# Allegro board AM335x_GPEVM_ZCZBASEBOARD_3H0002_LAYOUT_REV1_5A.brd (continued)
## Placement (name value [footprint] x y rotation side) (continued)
R585  10K  [SM-7351-RES-0402]  12.48 75.6 0 bottom
R586  220  [SM-7351-RES-0402]  14.13 86.78 0 top
R587  2.2K  [SM-7351-RES-0402]  11.98 87.92 0 top
R588  10K  [SM-7351-RES-0402]  14.13 87.92 0 top
R589  10K  [SM-7351-RES-0402]  9.05 50.2 180 top
R590  0  [SM-7351-RES-0402]  14.01 81.19 90 bottom
R591  4.7K  [SM-7351-RES-0402]  14.01 83.98 90 bottom
R592  0  [SM-7351-RES-0402]  18.58 68.49 90 top
R593  0  [SM-7351-RES-0402]  16.55 68.49 90 top
R594  100K  [SM-7351-RES-0402]  108.44 57.67 0 top
R595  0  [SM-7351-RES-0402]  104.81 56.55 0 top
R596  10K  [SM-7351-RES-0402]  108.11 52.93 270 bottom
R597  10K  [SM-7351-RES-0402]  110.15 52.93 90 bottom
R598  47  [SM-7351-RES-0402]  93.89 54.01 90 bottom
R599  47  [SM-7351-RES-0402]  90.84 66.71 270 bottom
R600  47  [SM-7351-RES-0402]  96.94 66.71 270 top
R601  47  [SM-7351-RES-0402]  92.87 66.71 270 bottom
R602  47  [SM-7351-RES-0402]  95.92 66.71 270 top
R603  10  [SM-7351-RES-0402]  102.53 51.22 180 bottom
R604  47  [SM-7351-RES-0402]  92.87 66.71 270 top
R605  47  [SM-7351-RES-0402]  86.52 54.01 90 bottom
R606  47  [SM-7351-RES-0402]  90.84 66.71 270 top
R607  47  [SM-7351-RES-0402]  91.86 66.71 270 top
R608  47  [SM-7351-RES-0402]  91.86 54.01 90 bottom
R609  47  [SM-7351-RES-0402]  89.83 66.71 270 top
R610  47  [SM-7351-RES-0402]  90.72 54.01 90 bottom
R611  47  [SM-7351-RES-0402]  89.83 66.71 270 bottom
R612  47  [SM-7351-RES-0402]  89.7 54.01 90 bottom
R613  47  [SM-7351-RES-0402]  88.81 66.71 270 top
R614  47  [SM-7351-RES-0402]  94.91 54.01 90 bottom
R615  47  [SM-7351-RES-0402]  85.51 54.01 90 bottom
R616  47  [SM-7351-RES-0402]  87.67 54.01 90 bottom
R617  47  [SM-7351-RES-0402]  88.81 66.71 270 bottom
R618  47  [SM-7351-RES-0402]  84.49 54.01 90 bottom
R619  47  [SM-7351-RES-0402]  88.68 54.01 90 bottom
R620  47  [SM-7351-RES-0402]  93.89 66.71 270 top
R621  47  [SM-7351-RES-0402]  92.87 54.01 90 bottom
R622  47  [SM-7351-RES-0402]  94.91 66.71 270 top
R623  47  [SM-7351-RES-0402]  91.86 66.71 270 bottom
R624  49.9  [SM-7351-RES-0402]  101 59.09 180 top
R625  49.9  [SM-7351-RES-0402]  101 60.11 180 top
R626  4.7K  [SM-7351-RES-0402]  6.51 50.71 90 top
R627  10K  [SM-7351-RES-0402]  12.86 83.98 270 bottom
R628  10K  [SM-7351-RES-0402]  86.52 27.34 270 bottom
R629  10K  [SM-7351-RES-0402]  13.63 16.17 0 top
R630  10K  [SM-7351-RES-0402]  87.54 62.14 270 bottom
R631  10K  [SM-7351-RES-0402]  78.14 54.27 270 bottom
R632  0  [SM-7351-RES-0402]  71.41 54.14 0 bottom
R634  10K  [SM-7351-RES-0402]  67.86 101.13 90 top
R635  0  [SM-7351-RES-0402]  71.64 57.95 90 top
R636  10K  [SM-7351-RES-0402]  71.41 55.16 0 bottom
SW1  Slide Switch  [TH_SW_T551101]  75.6 10.2 90 top
SW2  B3SL  [SW_B3SL-1022P]  8.8 62.14 270 top
SW3  Switch8pos  [219-8MST]  159.93 60.24 270 top
SW4  Switch8pos  [219-8MST]  159.93 82.84 270 top
SW5  B3SL  [SW_B3SL-1022P]  8.8 44.36 270 top
SW6  B3SL  [SW_B3SL-1022P]  7.4 14.13 0 top
TP23  TP1mm  [TP_SMD1MMCIRCLE]  93.13 98.59 0 top
TP24  TP1mm  [TP_SMD1MMCIRCLE]  69.25 78.02 270 top
TP25  TP  [TH_TP_5002]  88.81 20.36 0 top
TP26  TP  [TH_TP_5002]  100.88 42.07 180 top
TP27  TP  [TH_TP_5002]  4.99 70.4 0 top
TP28  TP  [TH_TP_5002]  167.55 91.35 0 top
TP29  TP  [TH_TP_5002]  91.86 2.7 0 top
TP30  TP  [TH_TP_5002]  85 167.55 0 top
TP31  TP1mm  [TP_SMD1MMCIRCLE]  67.92 95.86 270 top
TP32  TP1mm  [TP_SMD1MMCIRCLE]  63.03 92.87 0 top
TP35  TP1mm  [TP_SMD1MMCIRCLE]  77.38 122.85 180 bottom
TP36  TP1mm  [TP_SMD1MMCIRCLE]  91.35 96.3 0 top
TP38  TP1mm  [TP_SMD1MMCIRCLE]  43.47 61.38 0 top
TP39  TP1mm  [TP_SMD1MMCIRCLE]  43.47 59.98 0 top
TP40  TP1mm  [TP_SMD1MMCIRCLE]  43.47 57.82 0 top
TP41  TP1mm  [TP_SMD1MMCIRCLE]  43.47 56.43 0 top
TP42  TP1mm  [TP_SMD1MMCIRCLE]  14.64 112.94 180 bottom
TP43  TP1mm  [TP_SMD1MMCIRCLE]  13.5 113.58 180 bottom
TP44  TP1mm  [TP_SMD1MMCIRCLE]  14.77 114.21 180 bottom
TP45  TP1mm  [TP_SMD1MMCIRCLE]  3.47 137.45 180 bottom
TP46  TP1mm  [TP_SMD1MMCIRCLE]  31.91 64.43 0 top
TP47  TP1mm  [TP_SMD1MMCIRCLE]  33.18 64.43 0 top
TP48  TP1mm  [TP_SMD1MMCIRCLE]  34.45 64.43 0 top
TP49  TP1mm  [TP_SMD1MMCIRCLE]  35.72 64.43 0 top
TP50  TP1mm  [TP_SMD1MMCIRCLE]  36.36 51.22 180 bottom
TP51  TP1mm  [TP_SMD1MMCIRCLE]  21.12 13.25 0 top
TP52  TP1mm  [TP_SMD1MMCIRCLE]  23.91 75.98 0 top
TP53  TP1mm  [TP_SMD1MMCIRCLE]  85.25 37.5 0 top
TP54  TP  [TH_TP_5002]  139.23 59.85 0 top
U1  SN74AUP1G08  [U_5_DCK]  55.41 102.4 270 top
U2  AM335X_15x15  [AM33XX_15X15]  85 85 90 top
U4  TPS65910A3  [U_48_RSL]  89.45 33.69 90 top
U5  TPS71718  [SMDSC70-5]  84.11 22.52 0 top
U6  SN74AUP2G08  [U_8_DCU]  90.21 23.53 270 top
U7  CAT24C256W  [SOIC_8]  140.31 67.89 0 top
U9  MT29F2G08AB  [SKT-TSOP48SM]  149.01 106.59 90 top
U10  SIL9022A  [QFN_72]  140.88 33.44 180 top
U11  TPD12S016  [PW_24PIN_TSSOP]  140.5 15.02 270 top
U12  TPS71712  [SMDSC70-5]  148.63 18.83 180 top
U13  SN74AVC4T245  [U_16_PW]  23.28 118.4 90 top
U14  SN74AVC4T245  [U_16_PW]  23.28 124.75 90 top
U15  SN74AVC4T245  [U_16_PW]  23.28 137.45 90 top
U16  SN74AVC4T245  [U_16_PW]  23.28 131.1 90 top
U17  TPS79501  [SOT223_6PIN]  8.8 152.69 90 top
U18  MAX3232E  [U_16_D]  109.51 18.58 270 top
U19  TPD6E001  [U_10_RSE]  58.46 144.06 0 top
U20  TPD6E001  [U_10_RSE]  71.92 149.77 90 top
U21  TPD2E001  [U_5_DRL]  64.93 144.56 270 top
U22  TPS2051BD  [U_8_D]  135.42 147.55 0 top
U23  TPD4S012  [U_6_DRY]  132.37 162.32 0 top
U24  TPS63010  [U_20_DSBGA]  155.99 146.85 90 top
U25  AR8031_AL1A  [QFN48]  33.18 55.16 0 top
U26  SN74LVC1G07  [U_5_DCK]  24.17 61.51 90 top
U27  INA226  [SMDMSOP_10]  69.13 47.03 270 bottom
U28  TXS02612  [U_24_RTW]  23.02 108.62 270 top
U29  TPS2051BD  [U_8_D]  143.74 147.23 0 top
U30  TPD4S012  [U_6_DRY]  147.93 161.45 0 top
U32  INA226  [SMDMSOP_10]  64.36 35.15 270 top
U33  MT41J512M8THD  [DDR3_FBGA78PIN]  93.38 60.24 270 top
U34  MT41J512M8THD  [DDR3_FBGA78PIN]  78.78 60.24 270 top
U54  TPS79333  [U_5_DBV]  18.83 95.41 0 top
U55  SN74LVC1G00DCK  [U_5_DCK]  7.4 53.63 180 top
U57  TPD2E001  [U_5_DRL]  8.17 99.86 0 top
U58  FT2232HL  [LQFP64PIN]  15.02 78.27 0 top
U60  SN74LVC2G07  [U_6_DCK]  10.45 53.63 0 top
U61  93LC56B  [SOIC8]  11.85 92.62 90 top
U62  TPS51200  [DRCPSO_10PIN]  104.66 54.95 180 bottom
U63  TPS3808G01  [SOT23-6]  65.06 101 90 top
U64  SN74AVC1T45  [SMDSC70-6]  74.21 53.5 90 bottom
Y1  32.768KHz MC-306  [MC-306]  63.03 76.36 270 top
Y2  24MHz  [SM_CRY_SCC18]  105.7 81.83 0 top
Y3  25MHz  [SM_OSC_ABM3]  24.68 56.17 270 top
Y4  12MHz  [SM_OSC_ABM3]  4.99 85.64 270 top

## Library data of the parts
BT1 = Battery_coin3V
C1 C16 C17 C19 C23-C25 C29-C32 C35 C36 C43 C45-C48 C50 C52 C53 C61 C62 = 0.01uFCapacitor16V10%0402
C2 C3 = 25pFCapacitor100V5%0603
C4 C5 = 18pFCapacitor16V10%0402
C6-C8 C15 C18 C20 C27 C28 C34 C41 C42 C56 C63 C64 C66-C70 C73 C74 C76-C80 C82 C83 C87 C89 C90 C92-C94 C96 C98 C111 C114-C116 C125 C126 C128-C130 C136-C140 C149 C155-C158 C161-C170 C174 C175 C181 C183 C186 C188 C189 C195 C202 C203 C208 C213-C227 C313-C319 C321-C325 C327-C329 C331 = 0.01uFCapacitor16V10%0402: Tolerance: TOLERANCE; User Part Number: USERPART#
C9 = 0.1uFCapacitor16V10%0402
C10 C12 = 0.001uFCapacitor50V5%0402
C11 C13 C85 C86 C127 C131-C135 C141-C148 C150-C154 C176-C180 C187 C190 C193 C194 C196-C201 C209 C260 C264 C303-C309 C334-C336 C338 C339 C352-C357 C360-C379 = 0.1uFCapacitor16V10%0402: Tolerance: TOLERANCE; User Part Number: USERPART#
C14 C340 C341 = 0.001uFCapacitor50V5%0402: Tolerance: TOLERANCE; User Part Number: USERPART#
C60 = 1uFCapacitor10V10%0402
C65 C71 C72 C88 C112 C113 C117 C118 C159 C160 C173 C191 C192 = 1uFCapacitor10V10%0402: Tolerance: TOLERANCE; User Part Number: USERPART#
C84 = 100uFCapacitor16V20%ElectroPoly
C91 C97 C101-C104 C107-C110 C184 = 2.2uFCapacitor6.3V20%smdX5R0402: Tolerance: TOLERANCE; User Part Number: USERPART#
C171 = 15pFCapacitor50V10%smd0402: Tolerance: TOLERANCE; User Part Number: USERPART#
C172 C311 = 2.2uF16V10%SMD0805
C182 C185 = 150uFCapacitor10V10%2917
C204 C212 = 22pFCapacitor50V10%SMD0402: Tolerance: TOLERANCE; User Part Number: USERPART#
C205-C207 = 470pFCapacitor25V10%0402: Tolerance: TOLERANCE; User Part Number: USERPART#
C232-C249 C256-C259 C261 C266 C273-C279 C312 = 10uFCapacitor16V10%0805
C250-C255 = 4.7uFCapacitor6.3V20%smdX5R0603
C262 C263 C265 C320 C326 C330 C358 C359 = 4.7uFCapacitor16V10%0603
C267-C270 C280 = 22uFCapacitor16V10%0805
C271 C272 = 0.1uFCapacitor50V10%0402: Tolerance: TOLERANCE; User Part Number: USERPART#
C332 C333 = 18pFCapacitor16V10%0402: Tolerance: TOLERANCE; User Part Number: USERPART#
C337 = 10pFCapacitor50V1%smd0402: Tolerance: TOLERANCE; User Part Number: USERPART#
D1 = Diode_5ARect
D2 = Diode_SMCJ15CA
D3-D7 D11 = LED_Green
D8 = Diode200mA250V
D9 D10 = Diode_Zener_5.1V_100mW
F1 = Fuse_4A
FB1-FB14 FB19-FB21 FB25 = FerBead_180ohm200mA
FB15 FB16 = FerriteBead_600mA10ohm
FB22-FB24 = FerriteBead_220ohm2A
J1 = Conn_PwrJack_RAPC712
J2 = Header10x2_CJTAG
J3 J4 J6 J16 = Header_28pin_0.1in
J5 = Header_40pin_0.1in
J7-J9 = Header10x2_0.5inpitch_female
J10 = Conn_HDMI_TypeA
J11 = Conn_SamtecMEC6_150
J12 = Conn_DSUB9M_TH
J13 = Conn_SDCard_MHC-W21-601
J14 J40 = Conn_MicroUSBAB
J15 = ConnectorRJ45_Gigabit
J17 = Header_5x1
J18 = Connector_USB_A
J19 = Header20x1_wkey
J20-J39 J41 = Header_2x1
L2-L4 = 2.2uHInductor10%2.6Asmd
L5 L6 = ACM2012
L7 L8 = 4.7uH30%0.9Asmd
L9 = 4.7uHInductor30%3.1Asmd
Q1-Q4 = MOSFET_NChan_BSS138
Q5 = MOSFET_PChan_BSS84
R2 R3 R5 R8-R10 R30 R45 R51 R53 R55-R68 R73-R78 R84 R85 R87-R92 R113 R133-R157 R159 R161 R163 R165 R167 R169 R171 R173 R175-R184 R186 R187 R189 R191 R193 R194 R196-R230 R232-R234 R236 R240-R273 R278-R291 R293-R303 R305 R307 R308 R311-R325 R327 R328 R335-R358 R361-R364 R379 R380 R384 R385 R388 R389 R396-R402 R404 R405 R410 R423-R425 R427 R428 R430 R436-R452 R456-R460 R478 R479 R485-R492 R509-R512 R516 R550 R551 R556 R559-R562 R566 R571 R575-R583 R590 R592 R593 R595 R632 R635 = ZeroOhmResistor1/16W0402
R4 R86 R93-R111 R386 R391 R594 = 100KOhmResistor1/16W0402
R6 R48 R54 R72 R114-R132 R239 R274 R304 R306 R329-R334 R365-R373 R382 R383 R387 R393 R407 R409 R411-R414 R419 R422 R426 R431 R435 R455 R515 R518 R519 R544 R565 R569 R570 R585 R588 R589 R596 R597 R627-R631 R634 R636 = 10KOhmResistor1/16W0402
R7 = 1MOhmResistor1/16W0402
R22 R624 R625 = 49.9OhmResistor1/16W0402
R23 = 124Kohm1/16W1%SMD0402
R32 R46 = 0.05ohm0.5W1%Sense1206
R50 R80-R83 = 150ohm1/16W1%SMD0402
R69 R112 = 1KOhmResistor1/16W0402
R70 R71 R79 R275 R276 R326 R394 R453 R454 R547 R548 R552-R555 R591 R626 = 4.7KOhmResistor1/16W0402
R188 R231 R235 R237 R395 R415-R418 R420 R421 R432-R434 = 22OhmResistor1/16W1%0402
R277 = 51Kohm1/16W1%smd0402
R292 = 4.3KOhmResistor1/16W0402
R359 = 57.6Kohm1/10W1%smd0402
R360 = 30.1Kohm1/16W1%smd0402
R378 = 470Kohm1/16W1%SMD0402
R381 = 120Kohm1/16W1%SMD0402
R390 R392 R586 = 220ohm1/10W1%smd0402
R406 = 2.37KOhmResistor1/16W1%0402
R408 = 1.5KohmResistor1/16W5%smd0402
R461 R462 R517 = 100ohm1/16W1%SMD0402
R463-R477 R557 R558 = ZeroOhmResistor1/16W0603
R493-R496 R498 R508 R513 R545 R546 = 0.24ohm0.25W1%Sense0805
R497 R499 R500 R503-R507 = 2ohm0.25W1%Sense0805
R501 R502 = 1ohm0.25W1%Sense0805
R520 = 1.62MOhmResistor1/16W0402
R521 = 180KOhmResistor1/16W0402
R541 R542 R567 R568 R587 = 2.2KOhmResistor1/16W0402
R563 R564 = 1.2KohmResistor1/4W5%0805
R572 R573 = 240OhmResistor1/16W0402
R584 = 12Kohm1/16W1%SMD0402
R598-R602 R604-R623 = 47ohm1/16W1%smd0402
R603 = 10ohm1/16W5%smd0402
SW1 = Switch_SlideRA_SPDT
SW2 SW5 SW6 = Switch_Pushbuttonsmd
SW3 SW4 = SwitchDIP8pos_smd
TP23 TP24 TP31 TP32 TP35 TP36 TP38-TP53 = Testpoint_SMD1mmCircle
TP25-TP30 TP54 = TestPointThroughHole
U1 = SN74AUP1G08
U2 = AM335X_15mmx15mm
U4 = TPS65910A3
U5 = TPS71718
U6 = SN74AUP2G08
U7 = CAT24C256W
U9 = MT29F2G08ABBE
U10 = SIL9022A
U11 = TPD12S016
U12 = TPS71712
U13-U16 = SN74AVC4T245
U17 = TPS79501
U18 = MAX3232E
U19 U20 = TPD6E001RSE
U21 U57 = TPD2E001DRL
U22 U29 = TPS2051BD
U23 U30 = TPD4S012
U24 = TPS63010YFF
U25 = AR8031-AL1A_QFN48
U26 = SN74LVC1G07
U27 U32 = INA226
U28 = TXS02612
U33 U34 = MT41J512M8THD
U54 = TPS79333
U55 = SN74LVC1G00DCK
U58 = FT2232_2
U60 = SN74LVC2G07
U61 = 93C56EEPROM2Kbit: Tolerance: ***; User Part Number: ***
U62 = TPS51200
U63 = TPS3808G01
U64 = SN74AVC1T45
Y1 = Crystal_SMD32_768kHz
Y2 = Crystal24MHzSCC
Y3 = Crystal25MHzABM3
Y4 = Crystal12MHzABM3

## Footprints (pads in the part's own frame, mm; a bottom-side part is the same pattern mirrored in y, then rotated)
219-8MST
  rect 1.118x2.438 smd: 1(-8.89,-4.318) 2(-6.35,-4.318) 3(-3.81,-4.318) 4(-1.27,-4.318) 5(1.27,-4.318) 6(3.81,-4.318) 7(6.35,-4.318) 8(8.89,-4.318) 9(8.89,4.318) 10(6.35,4.318) 11(3.81,4.318) 12(1.27,4.318) 13(-1.27,4.318) 14(-3.81,4.318) 15(-6.35,4.318) 16(-8.89,4.318)
6605814-6
  round 1.422 hole 0.889: 1(0,0) 2(1.27,-2.54) 3(2.54,0) 4(3.81,-2.54) 5(5.08,0) 6(6.35,-2.54) 7(7.62,0) 8(8.89,-2.54) 9(10.16,0) 10(11.43,-2.54)
  round 1.397 hole 1.016: D1(-1.067,-11.43) D2(-1.067,-13.462) D3(12.497,-11.43) D4(12.497,-13.462)
  round 3.81 hole 3.175: M1(0,-8.89) M2(11.43,-8.89)
  round 2.159 hole 1.575: SHLD1(-2.032,-5.842) SHLD2(13.462,-5.842)
ACM2012H
  rect 0.75x0.35 smd: 1(-0.975,0.425) 2(-0.975,-0.425) 3(0.975,-0.425) 4(0.975,0.425)
AM33XX_15X15
  round 1.27 hole 1.778 unplated: (-9.238,8.863) (-9.238,-8.862) (8.487,8.863) (8.487,-8.862)
  round 1.397 hole 0.838 unplated: (-9.238,-3.782) (8.487,6.323)
  round 0.356 smd: A1(-6.8,6.8) A2(-6,6.8) A3(-5.2,6.8) A4(-4.4,6.8) A5(-3.6,6.8) A6(-2.8,6.8) A7(-2,6.8) A8(-1.2,6.8) A9(-0.4,6.8) A10(0.4,6.8) A11(1.2,6.8) A12(2,6.8) A13(2.8,6.8) A14(3.6,6.8) A15(4.4,6.8) A16(5.2,6.8) A17(6,6.8) A18(6.8,6.8) B1(-6.8,6) B2(-6,6) B3(-5.2,6) B4(-4.4,6) B5(-3.6,6) B6(-2.8,6) B7(-2,6) B8(-1.2,6) B9(-0.4,6) B10(0.4,6) B11(1.2,6) B12(2,6) B13(2.8,6) B14(3.6,6) B15(4.4,6) B16(5.2,6) B17(6,6) B18(6.8,6) C1(-6.8,5.2) C2(-6,5.2) C3(-5.2,5.2) C4(-4.4,5.2) C5(-3.6,5.2) C6(-2.8,5.2) C7(-2,5.2) C8(-1.2,5.2) C9(-0.4,5.2) C10(0.4,5.2) C11(1.2,5.2) C12(2,5.2) C13(2.8,5.2) C14(3.6,5.2) C15(4.4,5.2) C16(5.2,5.2) C17(6,5.2) C18(6.8,5.2) D1(-6.8,4.4) D2(-6,4.4) D3(-5.2,4.4) D4(-4.4,4.4) D5(-3.6,4.4) D6(-2.8,4.4) D7(-2,4.4) D8(-1.2,4.4) D9(-0.4,4.4) D10(0.4,4.4) D11(1.2,4.4) D12(2,4.4) D13(2.8,4.4) D14(3.6,4.4) D15(4.4,4.4) D16(5.2,4.4) D17(6,4.4) D18(6.8,4.4) E1(-6.8,3.6) E2(-6,3.6) E3(-5.2,3.6) E4(-4.4,3.6) E5(-3.6,3.6) E6(-2.8,3.6) E7(-2,3.6) E8(-1.2,3.6) E9(-0.4,3.6) E10(0.4,3.6) E11(1.2,3.6) E12(2,3.6) E13(2.8,3.6) E14(3.6,3.6) E15(4.4,3.6) E16(5.2,3.6) E17(6,3.6) E18(6.8,3.6) F1(-6.8,2.8) F2(-6,2.8) F3(-5.2,2.8) F4(-4.4,2.8) F5(-3.6,2.8) F6(-2.8,2.8) F7(-2,2.8) F8(-1.2,2.8) F9(-0.4,2.8) F10(0.4,2.8) F11(1.2,2.8) F12(2,2.8) F13(2.8,2.8) F14(3.6,2.8) F15(4.4,2.8) F16(5.2,2.8) F17(6,2.8) F18(6.8,2.8) G1(-6.8,2) G2(-6,2) G3(-5.2,2) G4(-4.4,2) G5(-3.6,2) G6(-2.8,2) G7(-2,2) G8(-1.2,2) G9(-0.4,2) G10(0.4,2) G11(1.2,2) G12(2,2) G13(2.8,2) G14(3.6,2) G15(4.4,2) G16(5.2,2) G17(6,2) G18(6.8,2) H1(-6.8,1.2) H2(-6,1.2) H3(-5.2,1.2) H4(-4.4,1.2) H5(-3.6,1.2) H6(-2.8,1.2) H7(-2,1.2) H8(-1.2,1.2) H9(-0.4,1.2) H10(0.4,1.2) H11(1.2,1.2) H12(2,1.2) H13(2.8,1.2) H14(3.6,1.2) H15(4.4,1.2) H16(5.2,1.2) H17(6,1.2) H18(6.8,1.2) J1(-6.8,0.4) J2(-6,0.4) J3(-5.2,0.4) J4(-4.4,0.4) J5(-3.6,0.4) J6(-2.8,0.4) J7(-2,0.4) J8(-1.2,0.4) J9(-0.4,0.4) J10(0.4,0.4) J11(1.2,0.4) J12(2,0.4) J13(2.8,0.4) J14(3.6,0.4) J15(4.4,0.4) J16(5.2,0.4) J17(6,0.4) J18(6.8,0.4) K1(-6.8,-0.4) K2(-6,-0.4) K3(-5.2,-0.4) K4(-4.4,-0.4) K5(-3.6,-0.4) K6(-2.8,-0.4) K7(-2,-0.4) K8(-1.2,-0.4) K9(-0.4,-0.4) K10(0.4,-0.4) K11(1.2,-0.4) K12(2,-0.4) K13(2.8,-0.4) K14(3.6,-0.4) K15(4.4,-0.4) K16(5.2,-0.4) K17(6,-0.4) K18(6.8,-0.4) L1(-6.8,-1.2) L2(-6,-1.2) L3(-5.2,-1.2) L4(-4.4,-1.2) L5(-3.6,-1.2) L6(-2.8,-1.2) L7(-2,-1.2) L8(-1.2,-1.2) L9(-0.4,-1.2) L10(0.4,-1.2) L11(1.2,-1.2) L12(2,-1.2) L13(2.8,-1.2) L14(3.6,-1.2) L15(4.4,-1.2) L16(5.2,-1.2) L17(6,-1.2) L18(6.8,-1.2) M1(-6.8,-2) M2(-6,-2) M3(-5.2,-2) M4(-4.4,-2) M5(-3.6,-2) M6(-2.8,-2) M7(-2,-2) M8(-1.2,-2) M9(-0.4,-2) M10(0.4,-2) M11(1.2,-2) M12(2,-2) M13(2.8,-2) M14(3.6,-2) M15(4.4,-2) M16(5.2,-2) M17(6,-2) M18(6.8,-2) N1(-6.8,-2.8) N2(-6,-2.8) N3(-5.2,-2.8) N4(-4.4,-2.8) N5(-3.6,-2.8) N6(-2.8,-2.8) N7(-2,-2.8) N8(-1.2,-2.8) N9(-0.4,-2.8) N10(0.4,-2.8) N11(1.2,-2.8) N12(2,-2.8) N13(2.8,-2.8) N14(3.6,-2.8) N15(4.4,-2.8) N16(5.2,-2.8) N17(6,-2.8) N18(6.8,-2.8) P1(-6.8,-3.6) P2(-6,-3.6) P3(-5.2,-3.6) P4(-4.4,-3.6) P5(-3.6,-3.6) P6(-2.8,-3.6) P7(-2,-3.6) P8(-1.2,-3.6) P9(-0.4,-3.6) P10(0.4,-3.6) P11(1.2,-3.6) P12(2,-3.6) P13(2.8,-3.6) P14(3.6,-3.6) P15(4.4,-3.6) P16(5.2,-3.6) P17(6,-3.6) P18(6.8,-3.6) R1(-6.8,-4.4) R2(-6,-4.4) R3(-5.2,-4.4) R4(-4.4,-4.4) R5(-3.6,-4.4) R6(-2.8,-4.4) R7(-2,-4.4) R8(-1.2,-4.4) R9(-0.4,-4.4) R10(0.4,-4.4) R11(1.2,-4.4) R12(2,-4.4) R13(2.8,-4.4) R14(3.6,-4.4) R15(4.4,-4.4) R16(5.2,-4.4) R17(6,-4.4) R18(6.8,-4.4) T1(-6.8,-5.2) T2(-6,-5.2) T3(-5.2,-5.2) T4(-4.4,-5.2) T5(-3.6,-5.2) T6(-2.8,-5.2) T7(-2,-5.2) T8(-1.2,-5.2) T9(-0.4,-5.2) T10(0.4,-5.2) T11(1.2,-5.2) T12(2,-5.2) T13(2.8,-5.2) T14(3.6,-5.2) T15(4.4,-5.2) T16(5.2,-5.2) T17(6,-5.2) T18(6.8,-5.2) U1(-6.8,-6) U2(-6,-6) U3(-5.2,-6) U4(-4.4,-6) U5(-3.6,-6) U6(-2.8,-6) U7(-2,-6) U8(-1.2,-6) U9(-0.4,-6) U10(0.4,-6) U11(1.2,-6) U12(2,-6) U13(2.8,-6) U14(3.6,-6) U15(4.4,-6) U16(5.2,-6) U17(6,-6) U18(6.8,-6) V1(-6.8,-6.8) V2(-6,-6.8) V3(-5.2,-6.8) V4(-4.4,-6.8) V5(-3.6,-6.8) V6(-2.8,-6.8) V7(-2,-6.8) V8(-1.2,-6.8) V9(-0.4,-6.8) V10(0.4,-6.8) V11(1.2,-6.8) V12(2,-6.8) V13(2.8,-6.8) V14(3.6,-6.8) V15(4.4,-6.8) V16(5.2,-6.8) V17(6,-6.8) V18(6.8,-6.8)
B520C-13-F
  rect 2.5x3.3 smd: 1(-3.4,0) 2(3.4,0)
CHKFOOTPRINT
  rect 0.8x1.8 smd: 1(-0.8,0) 2(0.8,0)
DDR3_FBGA78PIN
  round 0.33 smd: A1(-3.2,4.8) A2(-2.4,4.8) A3(-1.6,4.8) A7(1.6,4.8) A8(2.4,4.8) A9(3.2,4.8) B1(-3.2,4) B2(-2.4,4) B3(-1.6,4) B7(1.6,4) B8(2.4,4) B9(3.2,4) C1(-3.2,3.2) C2(-2.4,3.2) C3(-1.6,3.2) C7(1.6,3.2) C8(2.4,3.2) C9(3.2,3.2) D1(-3.2,2.4) D2(-2.4,2.4) D3(-1.6,2.4) D7(1.6,2.4) D8(2.4,2.4) D9(3.2,2.4) E1(-3.2,1.6) E2(-2.4,1.6) E3(-1.6,1.6) E7(1.6,1.6) E8(2.4,1.6) E9(3.2,1.6) F1(-3.2,0.8) F2(-2.4,0.8) F3(-1.6,0.8) F7(1.6,0.8) F8(2.4,0.8) F9(3.2,0.8) G1(-3.2,0) G2(-2.4,0) G3(-1.6,0) G7(1.6,0) G8(2.4,0) G9(3.2,0) H1(-3.2,-0.8) H2(-2.4,-0.8) H3(-1.6,-0.8) H7(1.6,-0.8) H8(2.4,-0.8) H9(3.2,-0.8) J1(-3.2,-1.6) J2(-2.4,-1.6) J3(-1.6,-1.6) J7(1.6,-1.6) J8(2.4,-1.6) J9(3.2,-1.6) K1(-3.2,-2.4) K2(-2.4,-2.4) K3(-1.6,-2.4) K7(1.6,-2.4) K8(2.4,-2.4) K9(3.2,-2.4) L1(-3.2,-3.2) L2(-2.4,-3.2) L3(-1.6,-3.2) L7(1.6,-3.2) L8(2.4,-3.2) L9(3.2,-3.2) M1(-3.2,-4) M2(-2.4,-4) M3(-1.6,-4) M7(1.6,-4) M8(2.4,-4) M9(3.2,-4) N1(-3.2,-4.8) N2(-2.4,-4.8) N3(-1.6,-4.8) N7(1.6,-4.8) N8(2.4,-4.8) N9(3.2,-4.8)
DRCPSO_10PIN
  rect 0.305x1.092 smd: 1(-1,-1.625) 2(-0.5,-1.625) 3(0,-1.625) 4(0.5,-1.625) 5(1,-1.625) 6(1,1.625) 7(0.5,1.625) 8(0,1.625) 9(-0.5,1.625) 10(-1,1.625)
  custom 0.412x0.412 smd: 11(0,0)
GMD2_2PIN
  rect 0.31x0.23 smd: 1(0,-0.19) 2(0,0.19)
HEADER10X2
  rect 0.711x2.87 smd: 1(-5.715,-2.705) 2(-5.715,2.705) 3(-4.445,-2.705) 4(-4.445,2.705) 5(-3.175,-2.705) 6(-3.175,2.705) 7(-1.905,-2.705) 8(-1.905,2.705) 9(-0.635,-2.705) 10(-0.635,2.705) 11(0.635,-2.705) 12(0.635,2.705) 13(1.905,-2.705) 14(1.905,2.705) 15(3.175,-2.705) 16(3.175,2.705) 17(4.445,-2.705) 18(4.445,2.705) 19(5.715,-2.705) 20(5.715,2.705)
HEADER20X1_0_100IN
  rect 1.524x1.524 hole 1.016: 1(0,0)
  round 1.524 hole 1.016: 2(2.54,0) 3(5.08,0) 5(10.16,0) 6(12.7,0) 7(15.24,0) 8(17.78,0) 9(20.32,0) 10(22.86,0) 11(25.4,0) 12(27.94,0) 13(30.48,0) 14(33.02,0) 15(35.56,0) 16(38.1,0) 17(40.64,0) 18(43.18,0) 19(45.72,0) 20(48.26,0)
HEADER_2X1
  rect 1.778x1.778 hole 1.016: 1(0,0)
  round 1.778 hole 1.016: 2(0,2.54)
HEADER_5X1
  rect 1.778x1.778 hole 1.016: 1(0,0)
  round 1.778 hole 1.016: 2(2.54,0) 3(5.08,0) 4(7.62,0) 5(10.16,0)
HEADER_10X2_TH
  oval 0.914x1.168 hole 0.66: 1(0,0) 2(0,1.27) 3(1.27,0) 4(1.27,1.27) 5(2.54,0) 6(2.54,1.27) 7(3.81,0) 8(3.81,1.27) 9(5.08,0) 10(5.08,1.27) 11(6.35,0) 12(6.35,1.27) 13(7.62,0) 14(7.62,1.27) 15(8.89,0) 16(8.89,1.27) 17(10.16,0) 18(10.16,1.27) 19(11.43,0) 20(11.43,1.27)
HF70ACB201209
  rect 1x1 smd: 1(-1,0) 2(1,0)
JUMP2X14-6040-1
  round 1.397 hole 1.016: 1(0,0) 2(0,2.54) 3(-2.54,0) 4(-2.54,2.54) 5(-5.08,0) 6(-5.08,2.54) 7(-7.62,0) 8(-7.62,2.54) 9(-10.16,0) 10(-10.16,2.54) 11(-12.7,0) 12(-12.7,2.54) 13(-15.24,0) 14(-15.24,2.54) 15(-17.78,0) 16(-17.78,2.54) 17(-20.32,0) 18(-20.32,2.54) 19(-22.86,0) 20(-22.86,2.54) 21(-25.4,0) 22(-25.4,2.54) 23(-27.94,0) 24(-27.94,2.54) 25(-30.48,0) 26(-30.48,2.54) 27(-33.02,0) 28(-33.02,2.54)
JUMP2X20-6040-1
  round 1.524 hole 1.016: 1(0,0) 2(0,2.54) 3(-2.54,0) 4(-2.54,2.54) 5(-5.08,0) 6(-5.08,2.54) 7(-7.62,0) 8(-7.62,2.54) 9(-10.16,0) 10(-10.16,2.54) 11(-12.7,0) 12(-12.7,2.54) 13(-15.24,0) 14(-15.24,2.54) 15(-17.78,0) 16(-17.78,2.54) 17(-20.32,0) 18(-20.32,2.54) 19(-22.86,0) 20(-22.86,2.54) 21(-25.4,0) 22(-25.4,2.54) 23(-27.94,0) 24(-27.94,2.54) 25(-30.48,0) 26(-30.48,2.54) 27(-33.02,0) 28(-33.02,2.54) 29(-35.56,0) 30(-35.56,2.54) 31(-38.1,0) 32(-38.1,2.54) 33(-40.64,0) 34(-40.64,2.54) 35(-43.18,0) 36(-43.18,2.54) 37(-45.72,0) 38(-45.72,2.54) 39(-48.26,0) 40(-48.26,2.54)
LQFP64PIN
  rect 1.5x0.3 smd: 1(-5.7,3.75) 2(-5.7,3.25) 3(-5.7,2.75) 4(-5.7,2.25) 5(-5.7,1.75) 6(-5.7,1.25) 7(-5.7,0.75) 8(-5.7,0.25) 9(-5.7,-0.25) 10(-5.7,-0.75) 11(-5.7,-1.25) 12(-5.7,-1.75) 13(-5.7,-2.25) 14(-5.7,-2.75) 15(-5.7,-3.25) 16(-5.7,-3.75) 33(5.7,-3.75) 34(5.7,-3.25) 35(5.7,-2.75) 36(5.7,-2.25) 37(5.7,-1.75) 38(5.7,-1.25) 39(5.7,-0.75) 40(5.7,-0.25) 41(5.7,0.25) 42(5.7,0.75) 43(5.7,1.25) 44(5.7,1.75) 45(5.7,2.25) 46(5.7,2.75) 47(5.7,3.25) 48(5.7,3.75)
  rect 0.3x1.5 smd: 17(-3.75,-5.7) 18(-3.25,-5.7) 19(-2.75,-5.7) 20(-2.25,-5.7) 21(-1.75,-5.7) 22(-1.25,-5.7) 23(-0.75,-5.7) 24(-0.25,-5.7) 25(0.25,-5.7) 26(0.75,-5.7) 27(1.25,-5.7) 28(1.75,-5.7) 29(2.25,-5.7) 30(2.75,-5.7) 31(3.25,-5.7) 32(3.75,-5.7) 49(3.75,5.7) 50(3.25,5.7) 51(2.75,5.7) 52(2.25,5.7) 53(1.75,5.7) 54(1.25,5.7) 55(0.75,5.7) 56(0.25,5.7) 57(-0.25,5.7) 58(-0.75,5.7) 59(-1.25,5.7) 60(-1.75,5.7) 61(-2.25,5.7) 62(-2.75,5.7) 63(-3.25,5.7) 64(-3.75,5.7)
MC-306
  rect 1.3x1.9 smd: 1(-2.75,-1.6) 2(2.75,-1.6) 3(2.75,1.6) 4(-2.75,1.6)
MEC6-150-02-S-D-RA1
  round 0.254 hole 1.549 unplated: (-18.345,0) (18.345,0)
  rect 0.4x2 smd: 1(-17.145,-4) 2(-17.145,4) 3(-16.51,-4) 4(-16.51,4) 5(-15.875,-4) 6(-15.875,4) 7(-15.24,-4) 8(-15.24,4) 9(-14.605,-4) 10(-14.605,4) 11(-13.97,-4) 12(-13.97,4) 13(-13.335,-4) 14(-13.335,4) 15(-12.7,-4) 16(-12.7,4) 17(-12.065,-4) 18(-12.065,4) 19(-11.43,-4) 20(-11.43,4) 21(-10.795,-4) 22(-10.795,4) 23(-10.16,-4) 24(-10.16,4) 25(-9.525,-4) 26(-9.525,4) 27(-8.89,-4) 28(-8.89,4) 29(-8.255,-4) 30(-8.255,4) 31(-7.62,-4) 32(-7.62,4) 33(-6.985,-4) 34(-6.985,4) 35(-6.35,-4) 36(-6.35,4) 37(-5.715,-4) 38(-5.715,4) 39(-5.08,-4) 40(-5.08,4) 41(-4.445,-4) 42(-4.445,4) 43(-3.81,-4) 44(-3.81,4) 45(-3.175,-4) 46(-3.175,4) 47(-2.54,-4) 48(-2.54,4) 49(-1.905,-4) 50(-1.905,4) 51(-1.27,-4) 52(-1.27,4) 53(-0.635,-4) 54(-0.635,4) 55(0,-4) 56(0,4) 57(0.635,-4) 58(0.635,4) 59(1.27,-4) 60(1.27,4) 61(1.905,-4) 62(1.905,4) 63(5.715,-4) 64(5.715,4) 65(6.35,-4) 66(6.35,4) 67(6.985,-4) 68(6.985,4) 69(7.62,-4) 70(7.62,4) 71(8.255,-4) 72(8.255,4) 73(8.89,-4) 74(8.89,4) 75(9.525,-4) 76(9.525,4) 77(10.16,-4) 78(10.16,4) 79(10.795,-4) 80(10.795,4) 81(11.43,-4) 82(11.43,4) 83(12.065,-4) 84(12.065,4) 85(12.7,-4) 86(12.7,4) 87(13.335,-4) 88(13.335,4) 89(13.97,-4) 90(13.97,4) 91(14.605,-4) 92(14.605,4) 93(15.24,-4) 94(15.24,4) 95(15.875,-4) 96(15.875,4) 97(16.51,-4) 98(16.51,4) 99(17.145,-4) 100(17.145,4)
MHC-W21-601-LF
  round 1.524 hole 1.092: (-11.5,-3.05)
  round 2.108 hole 1.6: (9.5,-3.05)
  rect 0.6x2 smd: 1(6.875,0) 2(4.375,0) 3(1.875,0) 4(-0.625,0) 5(-3.125,0) 6(-5.625,0) 7(-8.05,0) 8(-9.75,0) 9(9.375,0)
  rect 1x1.5 smd: 10(5.65,-17) 11(3.15,-17) 12(-4.35,-17) 13(-6.85,-17)
  rect 0.7x2 smd: 14(-12.25,0) 15(-11.05,0)
  rect 0.5x2 smd: 16(-7.27,0) 17(-6.475,0) 18(-4.775,0) 19(-1.475,0) 20(0.225,0) 21(1.025,0) 22(2.725,0) 23(3.525,0) 24(-8.9,0) 25(-3.975,0) 26(-2.275,0)
  rect 1.3x2.4 smd: 27(-14.15,-17.05) 28(14.15,-17.05)
MS920SE-FL27E
  rect 2.286x0.762 smd: 1(0,1) 2(0,-1)
NORCOMP_DB9M_TH
  rect 1.6x1.6 hole 1.092: 1(0.051,0)
  round 1.6 hole 1.092: 2(-2.718,0) 3(-5.486,0) 4(-8.255,0) 5(-11.024,0) 6(-1.346,2.845) 7(-4.102,2.845) 8(-6.871,2.845) 9(-9.639,2.845)
  round 5.08 hole 3.048: 10(-17.983,1.422) 11(7.01,1.422)
PW_24PIN_TSSOP
  rect 0.356x1.524 smd: 1(-3.575,-2.96) 2(-2.925,-2.96) 3(-2.275,-2.96) 4(-1.625,-2.96) 5(-0.975,-2.96) 6(-0.325,-2.96) 7(0.325,-2.96) 8(0.975,-2.96) 9(1.625,-2.96) 10(2.275,-2.96) 11(2.925,-2.96) 12(3.575,-2.96) 13(3.575,2.96) 14(2.925,2.96) 15(2.275,2.96) 16(1.625,2.96) 17(0.975,2.96) 18(0.325,2.96) 19(-0.325,2.96) 20(-0.975,2.96) 21(-1.625,2.96) 22(-2.275,2.96) 23(-2.925,2.96) 24(-3.575,2.96)
QFN48
  rect 0.8x0.2 smd: 1(-3.075,2.2) 2(-3.075,1.8) 3(-3.075,1.4) 4(-3.075,1) 5(-3.075,0.6) 6(-3.075,0.2) 7(-3.075,-0.2) 8(-3.075,-0.6) 9(-3.075,-1) 10(-3.075,-1.4) 11(-3.075,-1.8) 12(-3.075,-2.2) 25(3.075,-2.2) 26(3.075,-1.8) 27(3.075,-1.4) 28(3.075,-1) 29(3.075,-0.6) 30(3.075,-0.2) 31(3.075,0.2) 32(3.075,0.6) 33(3.075,1) 34(3.075,1.4) 35(3.075,1.8) 36(3.075,2.2)
  rect 0.2x0.8 smd: 13(-2.2,-3.075) 14(-1.8,-3.075) 15(-1.4,-3.075) 16(-1,-3.075) 17(-0.6,-3.075) 18(-0.2,-3.075) 19(0.2,-3.075) 20(0.6,-3.075) 21(1,-3.075) 22(1.4,-3.075) 23(1.8,-3.075) 24(2.2,-3.075) 37(2.2,3.075) 38(1.8,3.075) 39(1.4,3.075) 40(1,3.075) 41(0.6,3.075) 42(0.2,3.075) 43(-0.2,3.075) 44(-0.6,3.075) 45(-1,3.075) 46(-1.4,3.075) 47(-1.8,3.075) 48(-2.2,3.075)
  rect 3.8x3.8 smd: 49(0,0)
QFN_72
  oval 0.95x0.3 smd: 1(-4.95,4.25) 2(-4.95,3.75) 3(-4.95,3.25) 4(-4.95,2.75) 5(-4.95,2.25) 6(-4.95,1.75) 7(-4.95,1.25) 8(-4.95,0.75) 9(-4.95,0.25) 10(-4.95,-0.25) 11(-4.95,-0.75) 12(-4.95,-1.25) 13(-4.95,-1.75) 14(-4.95,-2.25) 15(-4.95,-2.75) 16(-4.95,-3.25) 17(-4.95,-3.75) 18(-4.95,-4.25) 37(4.95,-4.25) 38(4.95,-3.75) 39(4.95,-3.25) 40(4.95,-2.75) 41(4.95,-2.25) 42(4.95,-1.75) 43(4.95,-1.25) 44(4.95,-0.75) 45(4.95,-0.25) 46(4.95,0.25) 47(4.95,0.75) 48(4.95,1.25) 49(4.95,1.75) 50(4.95,2.25) 51(4.95,2.75) 52(4.95,3.25) 53(4.95,3.75) 54(4.95,4.25)
  oval 0.3x0.95 smd: 19(-4.25,-4.95) 20(-3.75,-4.95) 21(-3.25,-4.95) 22(-2.75,-4.95) 23(-2.25,-4.95) 24(-1.75,-4.95) 25(-1.25,-4.95) 26(-0.75,-4.95) 27(-0.25,-4.95) 28(0.25,-4.95) 29(0.75,-4.95) 30(1.25,-4.95) 31(1.75,-4.95) 32(2.25,-4.95) 33(2.75,-4.95) 34(3.25,-4.95) 35(3.75,-4.95) 36(4.25,-4.95) 55(4.25,4.95) 56(3.75,4.95) 57(3.25,4.95) 58(2.75,4.95) 59(2.25,4.95) 60(1.75,4.95) 61(1.25,4.95) 62(0.75,4.95) 63(0.25,4.95) 64(-0.25,4.95) 65(-0.75,4.95) 66(-1.25,4.95) 67(-1.75,4.95) 68(-2.25,4.95) 69(-2.75,4.95) 70(-3.25,4.95) 71(-3.75,4.95) 72(-4.25,4.95)
  rect 4.85x4.85 smd: EPAD(0,0)
RAPC712
  round 4.064 hole 3.556: 1(0,0)
  round 3.683 hole 3.048: 2(-2.997,-4.801) 3(-6.248,0)
SKT-TSOP48SM
  rect 1.524x0.305 smd: 1(-9.716,5.753) 2(-9.716,5.253) 3(-9.716,4.752) 4(-9.716,4.252) 5(-9.716,3.754) 6(-9.716,3.254) 7(-9.716,2.753) 8(-9.716,2.253) 9(-9.716,1.753) 10(-9.716,1.252) 11(-9.716,0.754) 12(-9.716,0.254) 13(-9.716,-0.246) 14(-9.716,-0.747) 15(-9.716,-1.247) 16(-9.716,-1.748) 17(-9.716,-2.248) 18(-9.716,-2.746) 19(-9.716,-3.246) 20(-9.716,-3.747) 21(-9.716,-4.247) 22(-9.716,-4.747) 23(-9.716,-5.248) 24(-9.716,-5.748) 25(9.716,-5.753) 26(9.716,-5.253) 27(9.716,-4.752) 28(9.716,-4.252) 29(9.716,-3.754) 30(9.716,-3.254) 31(9.716,-2.753) 32(9.716,-2.253) 33(9.716,-1.753) 34(9.716,-1.252) 35(9.716,-0.754) 36(9.716,-0.254) 37(9.716,0.246) 38(9.716,0.747) 39(9.716,1.247) 40(9.716,1.748) 41(9.716,2.248) 42(9.716,2.746) 43(9.716,3.246) 44(9.716,3.747) 45(9.716,4.247) 46(9.716,4.747) 47(9.716,5.248) 48(9.716,5.748)
SM-7351-CAP-0402
  round 0.635 smd: 1(-0.508,0) 2(0.508,0)
SM-7351-CAP-0603
  rect 1.092x1.041 smd: 1(-0.85,0) 2(0.85,0)
SM-7351-CAP-0805
  rect 1.346x1.524 smd: 1(-1,0) 2(1,0)
SM-7351-CAP-2917
  rect 2.413x2.54 smd: 1(3.175,0) 2(-3.175,0)
SM-7351-CAP-SMDCAN
  rect 4.15x1.65 smd: 1(3.05,0) 2(-3.05,0)
SM-7351-IND-0603
  rect 1.143x1.092 smd: 1(-0.9,0) 2(0.9,0)
SM-7351-IND-0805
  rect 1.397x1.549 smd: 1(-0.95,0) 2(0.95,0)
SM-7351-RES-0402
  round 0.635 smd: 1(-0.508,0) 2(0.508,0)
SM-7351-RES-0603
  rect 1.143x1.092 smd: 1(-0.9,0) 2(0.9,0)
SM-7351-RES-0805
  rect 1.143x1.549 smd: 1(-1.1,0) 2(1.1,0)
SM_CRY_SCC18
  rect 1.4x2.2 smd: 1(-1.25,3.2) 2(-1.25,-3.2) 3(1.25,-3.2) 4(1.25,3.2)
SM_LED_0805
  rect 1.15x1.194 smd: 1(1.125,0) 2(-1.125,0)
SM_OSC_ABM3
  rect 1.9x2.4 smd: 1(-2.05,0) 2(2.05,0)
SM_RES_0805_KELV
  rect 1.4x1.65 smd: 1(-1.3,0) 2(1.3,0)
  rect 0.127x0.127 smd: 3(-0.377,-1.186) 4(0.377,-1.186)
SM_RES_LVK12
  rect 1.75x1.1 smd: 1(-1.375,0.7) 2(1.375,0.7) 3(-1.375,-0.7) 4(1.375,-0.7)
SMCJ15CA
  rect 2.4x3.3 smd: 1(-3.3,0) 2(3.3,0)
SMD_HDMIA_RA
  rect 0.3x1.9 smd: 1(4.75,0) 2(4.25,0) 3(3.75,0) 4(3.25,0) 5(2.75,0) 6(2.25,0) 7(1.75,0) 8(1.25,0) 9(0.75,0) 10(0.25,0) 11(-0.25,0) 12(-0.75,0) 13(-1.25,0) 14(-1.75,0) 15(-2.25,0) 16(-2.75,0) 17(-3.25,0) 18(-3.75,0) 19(-4.25,0)
  round 1.778 hole 1.27: MTG1(-7.25,-1) MTG2(7.25,-1) MTG3(-7.85,-5.9) MTG4(7.85,-5.9)
SMD_SLF7055T
  rect 1.5x2.2 smd: 1(-3.15,0) 2(3.15,0)
SMDFUSEBLK
  rect 4.242x3.81 smd: 1(-3.175,0) 2(3.175,0)
SMDMSOP_10
  rect 0.254x1.016 smd: 1(-1,-2.5) 2(-0.5,-2.5) 3(0,-2.5) 4(0.5,-2.5) 5(1,-2.5) 6(1,2.5) 7(0.5,2.5) 8(0,2.5) 9(-0.5,2.5) 10(-1,2.5)
SMDSC70-5
  rect 0.406x1.016 smd: 1(-0.65,-0.95) 2(0,-0.95) 3(0.65,-0.95) 4(0.65,0.95) 5(-0.65,0.95)
SMDSC70-6
  rect 0.381x0.762 smd: 1(-0.65,-0.953) 2(0,-0.953) 3(0.65,-0.953) 4(0.65,0.953) 5(0,0.953) 6(-0.65,0.953)
SOD-123
  rect 0.914x1.219 smd: 1(1.651,0) 2(-1.651,0)
SOIC8
  rect 1.27x0.635 smd: 1(-2.477,1.905) 2(-2.477,0.635) 3(-2.477,-0.635) 4(-2.477,-1.905) 5(2.477,-1.905) 6(2.477,-0.635) 7(2.477,0.635) 8(2.477,1.905)
SOIC_8
  rect 0.61x2.184 smd: 1(-1.905,-2.603)
  oval 0.61x2.184 smd: 2(-0.635,-2.603) 3(0.635,-2.603) 4(1.905,-2.603) 5(1.905,2.603) 6(0.635,2.603) 7(-0.635,2.603) 8(-1.905,2.603)
SOT23-3
  rect 0.787x0.889 smd: D(0,1.003) G(-0.94,-1.003) S(0.94,-1.003)
SOT23-6
  rect 0.635x1.016 smd: 1(-0.953,-1.295) 2(0,-1.295) 3(0.953,-1.295) 4(0.953,1.295) 5(0,1.295) 6(-0.953,1.295)
SOT223_6PIN
  rect 0.991x1.499 smd: 1(-2.54,-3.15) 2(-1.27,-3.15) 3(0,-3.15) 4(1.27,-3.15) 5(2.54,-3.15)
  rect 3.277x1.499 smd: 6(0,3.15)
SW_B3SL-1022P
  rect 2.75x1 smd: 1(2.875,-2) 2(-2.875,-2) 3(2.875,2) 4(-2.875,2)
TH_SW_T551101
  round 1.524 hole 1.092: 1(0,0) 2(0,-2.54) 3(0,-5.08) M1(-5.08,0) M2(-5.08,-5.08)
TH_TP_5002
  round 1.778 hole 1.016: 1(0,0)
TP_SMD1MMCIRCLE
  round 1.016 smd: 1(0,0)
U_5_DBV
  rect 0.686x0.991 smd: 1(-0.953,-1.295) 2(0,-1.295) 3(0.953,-1.295) 4(0.953,1.295) 5(-0.953,1.295)
U_5_DCK
  rect 0.432x1.27 smd: 1(0.65,0.775) 2(0,0.775) 3(-0.65,0.775) 4(-0.65,-0.884) 5(0.65,-0.884)
U_5_DRL
  rect 0.3x0.45 smd: 1(-0.5,-0.675) 2(0,-0.675) 3(0.5,-0.675) 4(0.5,0.675) 5(-0.5,0.675)
U_6_DCK
  rect 0.432x1.27 smd: 1(0.65,0.775) 2(0,0.775) 3(-0.65,0.775) 4(-0.65,-0.884) 5(0,-0.884) 6(0.65,-0.884)
U_6_DRY
  rect 0.305x0.508 smd: 1(-0.5,-0.439) 2(0,-0.439) 3(0.5,-0.439) 4(0.5,0.439) 5(0,0.439) 6(-0.5,0.439)
U_8_D
  rect 0.6x2 smd: 1(-1.905,-2.4) 2(-0.635,-2.4) 3(0.635,-2.4) 4(1.905,-2.4) 5(1.905,2.4) 6(0.635,2.4) 7(-0.635,2.4) 8(-1.905,2.4)
U_8_DCU
  rect 0.254x1.27 smd: 1(-0.749,-1.473) 2(-0.249,-1.473) 3(0.249,-1.473) 4(0.749,-1.473) 5(0.749,1.473) 6(0.249,1.473) 7(-0.249,1.473) 8(-0.749,1.473)
U_10_RSE
  rect 0.3x0.58 smd: 1(-0.75,-0.635) 2(-0.25,-0.635) 3(0.25,-0.635) 4(0.75,-0.635) 6(0.75,0.635) 7(0.25,0.635) 8(-0.25,0.635) 9(-0.75,0.635)
  rect 0.63x0.35 smd: 5(0.86,0) 10(-0.86,0)
U_16_D
  rect 0.6x2 smd: 1(-4.445,-2.4) 2(-3.175,-2.4) 3(-1.905,-2.4) 4(-0.635,-2.4) 5(0.635,-2.4) 6(1.905,-2.4) 7(3.175,-2.4) 8(4.445,-2.4) 9(4.445,2.4) 10(3.175,2.4) 11(1.905,2.4) 12(0.635,2.4) 13(-0.635,2.4) 14(-1.905,2.4) 15(-3.175,2.4) 16(-4.445,2.4)
U_16_PW
  rect 0.35x1.6 smd: 1(-2.275,-2.8) 2(-1.625,-2.8) 3(-0.975,-2.8) 4(-0.325,-2.8) 5(0.325,-2.8) 6(0.975,-2.8) 7(1.625,-2.8) 8(2.275,-2.8) 9(2.275,2.8) 10(1.625,2.8) 11(0.975,2.8) 12(0.325,2.8) 13(-0.325,2.8) 14(-0.975,2.8) 15(-1.625,2.8) 16(-2.275,2.8)
U_20_DSBGA
  round 0.254 smd: A1(0.6,-0.8) A2(0.2,-0.8) A3(-0.2,-0.8) A4(-0.6,-0.8) B1(0.6,-0.4) B2(0.2,-0.4) B3(-0.2,-0.4) B4(-0.6,-0.4) C1(0.6,0) C2(0.2,0) C3(-0.2,0) C4(-0.6,0) D1(0.6,0.4) D2(0.2,0.4) D3(-0.2,0.4) D4(-0.6,0.4) E1(0.6,0.8) E2(0.2,0.8) E3(-0.2,0.8) E4(-0.6,0.8)
U_24_RTW
  rect 0.85x0.28 smd: 1(-1.975,1.25) 2(-1.975,0.75) 3(-1.975,0.25) 4(-1.975,-0.25) 5(-1.975,-0.75) 6(-1.975,-1.25) 13(1.975,-1.25) 14(1.975,-0.75) 15(1.975,-0.25) 16(1.975,0.25) 17(1.975,0.75) 18(1.975,1.25)
  rect 0.28x0.85 smd: 7(-1.25,-1.975) 8(-0.75,-1.975) 9(-0.25,-1.975) 10(0.25,-1.975) 11(0.75,-1.975) 12(1.25,-1.975) 19(1.25,1.975) 20(0.75,1.975) 21(0.25,1.975) 22(-0.25,1.975) 23(-0.75,1.975) 24(-1.25,1.975)
  rect 2.45x2.45 smd: TPAD(0,0)
U_48_RSL
  rect 0.85x0.2 smd: 1(-2.975,2.2) 2(-2.975,1.8) 3(-2.975,1.4) 4(-2.975,1) 5(-2.975,0.6) 6(-2.975,0.2) 7(-2.975,-0.2) 8(-2.975,-0.6) 9(-2.975,-1) 10(-2.975,-1.4) 11(-2.975,-1.8) 12(-2.975,-2.2) 25(2.975,-2.2) 26(2.975,-1.8) 27(2.975,-1.4) 28(2.975,-1) 29(2.975,-0.6) 30(2.975,-0.2) 31(2.975,0.2) 32(2.975,0.6) 33(2.975,1) 34(2.975,1.4) 35(2.975,1.8) 36(2.975,2.2)
  rect 0.2x0.85 smd: 13(-2.2,-2.975) 14(-1.8,-2.975) 15(-1.4,-2.975) 16(-1,-2.975) 17(-0.6,-2.975) 18(-0.2,-2.975) 19(0.2,-2.975) 20(0.6,-2.975) 21(1,-2.975) 22(1.4,-2.975) 23(1.8,-2.975) 24(2.2,-2.975) 37(2.2,2.975) 38(1.8,2.975) 39(1.4,2.975) 40(1,2.975) 41(0.6,2.975) 42(0.2,2.975) 43(-0.2,2.975) 44(-0.6,2.975) 45(-1,2.975) 46(-1.4,2.975) 47(-1.8,2.975) 48(-2.2,2.975)
  rect 4.05x4.05 smd: PPAD(-0.225,0.225)
unnamed#2
  round 1.27 hole 6.35 unplated: (0,0)
USB_STD_A_TH
  round 1.676 hole 0.914: 1(0,0) 2(2.5,0) 3(4.5,0) 4(7,0)
  round 2.794 hole 2.311: S1(-3.073,-2.718) S2(10.058,-2.718)
VLCF5020T
  custom 0.525x0.525 smd: 1(-1.7,0) 2(1.7,0)
ZX62-AB-5PA
  rect 1.9x1.9 smd: (-1.2,-2.675) (1.2,-2.675)
  rect 0.4x1.35 smd: 1(-1.3,0) 2(-0.65,0) 3(0,0) 4(0.65,0) 5(1.3,0)
  rect 2.1x1.6 smd: S1(-3.1,-0.125) S2(3.1,-0.125)
  rect 1.8x1.9 smd: S3(-4.1,-2.675) S4(4.1,-2.675)

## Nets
DGND: BT1.2(NEG) C1.2 C6.2 C7.2 C8.2 C15.2 C16.2 C17.2 C18.2 C19.2 C20.2 C23.2 C24.2 C25.2 C27.2 C28.2 C29.2 C30.2 C31.2 C32.2 C34.2 C35.2 C36.2 C41.2 C42.2 C43.2 C45.2 C46.2 C47.2 C48.2 C50.2 C52.2 C53.2 C56.2 C60.2 C61.2 C62.2 C64.2 C65.2 C66.2 C68.2 C69.2 C70.2 C71.2 C72.2 C73.2 C74.2 C76.2 C77.2 C78.2 C79.2 C80.2 C82.2 C83.2 C84.2(NEG) C85.2 C86.2 C87.2 C88.2 C89.2 C90.2 C91.2 C92.2 C93.2 C94.2 C96.2 C97.2 C98.2 C101.2 C102.2 C103.2 C104.2 C107.2 C108.2 C109.2 C110.2 C111.2 C112.2 C113.2 C114.2 C115.2 C116.2 C117.2 C118.2 C125.2 C126.2 C127.2 C128.2 C129.2 C130.2 C131.2 C132.2 C133.2 C134.2 C135.2 C136.2 C137.2 C138.2 C139.2 C140.2 C141.2 C142.2 C143.2 C144.2 C145.2 C146.2 C147.2 C148.2 C149.2 C150.2 C151.2 C152.2 C153.2 C154.2 C155.2 C156.2 C157.2 C158.2 C159.2 C160.2 C161.2 C162.2 C163.2 C164.2 C165.2 C166.2 C167.2 C168.2 C169.2 C170.2 C172.2 C173.2 C174.2 C175.2 C177.2 C179.2 C180.2 C181.2 C182.2(NEG) C183.2 C184.2 C185.2(NEG) C186.2 C187.2 C188.2 C189.2 C190.2 C191.2 C192.2 C193.2 C194.2 C195.2 C196.2 C197.2 C198.2 C199.2 C200.2 C201.2 C202.2 C203.2 C204.1 C205.2 C206.2 C207.2 C208.2 C209.2 C212.1 C213.2 C214.2 C215.2 C216.2 C217.2 C218.2 C219.2 C220.2 C221.2 C222.2 C223.2 C224.2 C225.2 C226.2 C227.2 C232.2 C233.2 C234.2 C235.2 C236.2 C237.2 C238.2 C239.2 C240.2 C241.2 C242.2 C243.2 C244.2 C245.2 C246.2 C247.2 C248.2 C249.2 C250.2 C251.2 C252.2 C253.2 C254.2 C255.2 C256.2 C257.2 C258.2 C259.2 C260.2 C261.2 C262.2 C263.2 C264.2 C265.2 C266.2 C267.2 C268.2 C269.2 C270.2 C271.1 C272.1 C273.2 C274.2 C275.2 C276.2 C277.2 C278.2 C279.2 C280.2 C303.2 C304.2 C305.2 C306.2 C307.2 C308.2 C311.2 C312.2 C313.2 C314.2 C315.2 C316.2 C317.2 C318.1 C319.1 C320.1 C321.2 C322.2 C323.1 C324.2 C325.2 C326.1 C327.2 C328.2 C329.1 C330.2 C331.1 C332.2 C333.2 C334.2 C337.2 C338.2 C339.2 C340.2 C341.2 C354.2 C357.2 C358.2 C359.2 C376.2 C377.2 D2.2(ANODE) D3.1(CATHODE) D9.2(ANODE) D10.2(ANODE) FB10.2 FB14.1 FB19.1 FB25.2 J1.2 J1.3 J2.8(GND#8) J2.10(GND#10) J2.12(GND#12) J2.16(GND#16) J2.20(GND#20) J3.27 J3.28 J4.7 J4.8 J5.1 J5.10 J5.11 J5.20 J5.30 J5.37 J6.3 J6.14 J6.20 J6.25 J7.19 J7.20 J8.19 J8.20 J9.10 J10.2(DAT2_S) J10.5(DAT1_S) J10.8(DAT0_S) J10.11(CLK_S) J10.17(DDC/CEC GND) J10.MTG1 J10.MTG2 J10.MTG3 J10.MTG4 J11.2 J11.3 J11.6 J11.9 J11.18 J11.19 J11.22 J11.35 J11.37 J11.39 J11.42 J11.47 J11.60 J11.63 J11.64 J11.77 J11.83 J11.87 J11.92 J11.95 J11.97 J12.5 J12.10 J12.11 J13.3(#3_MMC+/MMCM/RSMMC/MMC/SD) J13.6(#6_MMC+/MMCM/RSMMC/MMC/SD) J13.18(#3_MINISD) J13.21(#6_MINISD) J13.27(GND1) J13.28(GND2) J14.5(GND) J15.1 J15.D2 J15.D3 J16.15 J16.27 J16.28 J17.3 J18.4(GND) J19.5 J19.10 J19.19 J19.20 J40.5(GND) Q1.S(SOURCE) Q2.S(SOURCE) Q3.S(SOURCE) Q4.S(SOURCE) R4.1(P1) R22.1(P1) R48.1(P1) R64.2(P2) R73.1(P1) R79.1(P1) R86.1(P1) R93.1(P1) R94.1(P1) R95.1(P1) R112.1(P1) R114.1(P1) R115.1(P1) R116.1(P1) R117.1(P1) R118.1(P1) R119.1(P1) R120.1(P1) R121.1(P1) R122.1(P1) R123.1(P1) R124.1(P1) R125.1(P1) R126.1(P1) R127.1(P1) R128.1(P1) R129.1(P1) R274.1(P1) R292.1(P1) R304.1(P1) R308.1(P1) R325.1(P1) R326.1(P1) R360.1(P1) R381.1(P1) R383.2(P2) R385.1(P1) R387.2(P2) R406.1(P1) R411.1(P1) R413.1(P1) R414.1(P1) R419.1(P1) R422.1(P1) R426.1(P1) R431.1(P1) R435.1(P1) R516.1(P1) R521.1(P1) R541.1(P1) R569.1(P1) R572.1(P1) R573.1(P1) R584.2(P2) R592.1(P1) R596.1(P1) R626.1(P1) R627.1(P1) R636.1(P1) SW1.M1 SW1.M2 SW2.1 SW2.2 SW6.1 SW6.2 TP27.1 TP28.1 TP29.1 TP30.1 U1.3(GND) U2.A1(VSS#A1) U2.A18(VSS#A18) U2.F8(VSS#F8) U2.G8(VSS#G8) U2.G9(VSS#G9) U2.G11(VSS#G11) U2.G12(VSS#G12) U2.H6(VSS#H6) U2.H7(VSS#H7) U2.H8(VSS#H8) U2.H9(VSS#H9) U2.H10(VSS#H10) U2.H12(VSS#H12) U2.J6(VSS#J6) U2.J7(VSS#J7) U2.J8(VSS#J8) U2.J9(VSS#J9) U2.J10(VSS#J10) U2.J11(VSS#J11) U2.K7(VSS#K7) U2.K9(VSS#K9) U2.K10(VSS#K10) U2.K11(VSS#K11) U2.L10(VSS#L10) U2.L11(VSS#L11) U2.L12(VSS#L12) U2.L13(VSS#L13) U2.M6(VSS#M6) U2.M7(VSS#M7) U2.M8(VSS#M8) U2.M9(VSS#M9) U2.M10(VSS#M10) U2.M12(VSS#M12) U2.M14(VSSA_USB#M14) U2.N7(VSS#N7) U2.N10(VSS#N10) U2.N11(VSS#N11) U2.N14(VSSA_USB#N14) U2.V1(VSS#V1) U2.V18(VSS#V18) U4.15(GNDIO) U4.17(REFGND) U4.34(GND1) U4.43(GND2) U4.PPAD(GNDP) U5.2(GND) U6.4(GND) U6.5(2A) U6.6(2B) U7.1(A0) U7.2(A1) U7.3(A2) U7.4(VSS) U9.13(GND#13) U9.25(GND#25) U9.36(GND#36) U9.48(GND#48) U10.43(CGND) U10.55(RSVDL) U10.57(IOGND) U10.63(AGND) U10.70(VDDQ) U10.EPAD U11.6(GND#6) U11.14(GND#14) U11.19(GND#19) U12.2(GND) U13.2(1DIR) U13.8(GND#8) U13.9(GND#9) U13.14(2O\E\) U13.15(1O\E\) U14.3(2DIR) U14.8(GND#8) U14.9(GND#9) U14.14(2O\E\) U14.15(1O\E\) U15.8(GND#8) U15.9(GND#9) U15.14(2O\E\) U15.15(1O\E\) U16.3(2DIR) U16.8(GND#8) U16.9(GND#9) U16.14(2O\E\) U16.15(1O\E\) U17.3(GND#3) U17.6(GND#6) U18.15(GND) U19.5(GND) U20.5(GND) U21.4(GND) U22.1(GND) U23.4(GND) U24.B4(SYNC) U24.C1(PGND#C1) U24.C2(PGND#C2) U24.C3(GND#C3) U24.D3(GND#D3) U24.E4(GND#E4) U25.49(EP) U26.3(GND) U27.1(A1) U27.2(A0) U27.7(GND) U28.2(GND#2) U28.11(GND#11) U28.TPAD U29.1(GND) U30.4(GND) U32.1(A1) U32.7(GND) U33.A1(VSS#A1) U33.A8(VSS#A8) U33.B1(VSS#B1) U33.B2(VSSQ#B2) U33.B8(VSSQ#B8) U33.C9(VSSQ#C9) U33.D1(VSSQ#D1) U33.D8(VSS#D8) U33.D9(VSSQ#D9) U33.F2(VSS#F2) U33.F8(VSS#F8) U33.J1(VSS#J1) U33.J9(VSS#J9) U33.L1(VSS#L1) U33.L9(VSS#L9) U33.N1(VSS#N1) U33.N9(VSS#N9) U34.A1(VSS#A1) U34.A8(VSS#A8) U34.B1(VSS#B1) U34.B2(VSSQ#B2) U34.B8(VSSQ#B8) U34.C9(VSSQ#C9) U34.D1(VSSQ#D1) U34.D8(VSS#D8) U34.D9(VSSQ#D9) U34.F2(VSS#F2) U34.F8(VSS#F8) U34.J1(VSS#J1) U34.J9(VSS#J9) U34.L1(VSS#L1) U34.L9(VSS#L9) U34.N1(VSS#N1) U34.N9(VSS#N9) U54.2(GND) U55.3(GND) U57.4(GND) U58.1(GND.1) U58.5(GND.2) U58.10(AGND) U58.11(GND.3) U58.13(TEST) U58.15(GND.4) U58.25(GND.5) U58.35(GND.6) U58.47(GND.7) U58.51(GND.8) U60.2(GND) U61.5(VSS) U61.7(NC1) U62.4(PGND) U62.8(GND) U62.11(PWRPD) U63.2(GND) U64.2(GND) U64.5(DIR)
GND_ETH: C271.2 C272.2 J15.SHLD1 J15.SHLD2
GND_OSC0: C4.2 C5.2 C67.2 U2.V11(VSS_OSC)
GND_OSC1: C2.1 C3.1 U2.A5(VSS_RTC)
GNDA_ADC: C63.2 FB10.1 R45.1(P1) R461.1(P1) U2.E8(VSSA_ADC)
GNDA_TSC: C11.2 C12.2 C13.2 C14.2 J9.11 J9.12 R45.2(P2) R51.2(P2)
GNDUSB0: FB14.2 J14.S1 J14.S2 J14.S3 J14.S4
GNDUSB1: FB19.2 J18.S1 J18.S2
GNDUSBJ: FB25.1 J40.S1 J40.S2 J40.S3 J40.S4
V1_2D: C159.1 C242.1 C268.1 FB11.2 FB13.2 U12.5(OUT)
V1_2D_EN: R478.1(P1) U12.3(EN)
V1_8D: C87.1 C133.1 C138.1 C162.1 C164.1 C166.1 C168.1 C170.1 C261.1 J3.1 J8.2 J11.8 J11.62 R329.2(P2) R330.2(P2) R331.2(P2) R332.2(P2) R333.2(P2) R334.2(P2) R358.2(P2) R472.1(P1) R519.2(P2) U13.16(VCCB) U14.16(VCCB) U15.16(VCCB) U16.16(VCCB) U28.17(VCCB1)
V1_8FTDI: C316.1 C321.1 C324.1 C327.1 C330.1 U58.12(VCORE.1) U58.37(VCORE.2) U58.49(VREGOUT) U58.64(VCORE.3)
V3_3D: C134.1 C135.1 C140.1 C175.1 C190.1 C191.1 C215.1 C222.1 C245.1 C318.2 C319.2 C358.1 C359.1 FB15.1 J5.39 J6.15 J9.2 R68.1(P1) R386.2(P2) R453.2(P2) R454.2(P2) R455.2(P2) R544.2(P2) R593.1(P1) U18.16(VCC) U25.4(VDD33) U27.6(VS) U32.6(VS) U54.3(EN) U55.5(VCC) U60.5(VCC)
V3_3ETHJCK: J15.2 TP51.1
V3_3FTDI: C311.1 C317.1 C322.1 C325.1 C328.1 C331.2 C334.1 FB23.2 FB24.2 R585.2(P2) R588.2(P2) U54.5(OUT) U58.20(VCCIO.1) U58.31(VCCIO.2) U58.42(VCCIO.3) U58.50(VREGIN) U58.56(VCCIO.4) U61.6(NC2) U61.8(VCC)
V5_0D: C132.1 C136.1 C137.1 C157.1 C184.1 C269.1 C270.1 J3.2 J7.1 J7.2 R275.2(P2) R276.2(P2) R520.2(P2) U11.11(VCC5V) U22.2(IN#2) U22.3(IN#3) U24.E1(VOUT#E1) U24.E2(VOUT#E2) U29.2(IN#2) U29.3(IN#3)
V5_0D_EN: R386.1(P1) U24.A4(EN)
V5_0HDMICONN: C158.1 J10.18(+5V) U11.13(5V_OUT)
VBAT: C8.1 C84.1(POS) C85.1 C86.1 C88.1 C112.1 C139.1 C141.1 C160.1 C173.1 C187.1 C214.1 C234.1 C236.1 C238.1 C240.1 C250.1 C251.1 C252.1 C253.1 C254.1 C263.1 C312.1 J6.19 J8.1 J16.5 J19.1 J19.2 R50.2(P2) R80.2(P2) R81.2(P2) R82.2(P2) R83.2(P2) R239.2(P2) R629.2(P2) SW1.2 TP25.1 U4.3(VCC3) U4.6(VCC6) U4.13(VCCIO) U4.23(VCC5) U4.28(VCC7) U4.36(VCC1) U4.41(VCC2) U4.47(VCC4) U5.1(IN) U5.3(EN) U12.1(IN) U17.2(IN) U24.A1(VIN#A1) U24.A2(VIN#A2) U54.1(IN) U63.6(VDD)
VBUS0_OTG_CAP: C182.1(POS) J36.2
VBUS1_OTG_CAP: C185.1(POS) J37.2 R558.2(P2)
VDD1_SMPS: C357.1 J19.6 R46.1(I1) R469.1(P1) U32.8(VBUS)
VDD2_SMPS: C6.1 C354.1 J19.7 R32.1(I1) R468.1(P1) U27.8(VBUS) U63.5(SENSE)
VDD3_SMPS: C235.1 J19.8 R470.1(P1)
VDD_CORE: C16.1 C17.1 C19.1 C23.1 C24.1 C34.1 C35.1 C36.1 C232.1 R32.2(I2) U2.F6(VDD_CORE#F6) U2.F7(VDD_CORE#F7) U2.G6(VDD_CORE#G6) U2.G7(VDD_CORE#G7) U2.G10(VDD_CORE#G10) U2.H11(VDD_CORE#H11) U2.J12(VDD_CORE#J12) U2.K6(VDD_CORE#K6) U2.K8(VDD_CORE#K8) U2.K12(VDD_CORE#K12) U2.L6(VDD_CORE#L6) U2.L7(VDD_CORE#L7) U2.L8(VDD_CORE#L8) U2.L9(VDD_CORE#L9) U2.M11(VDD_CORE#M11) U2.M13(VDD_CORE#M13) U2.N8(VDD_CORE#N8) U2.N9(VDD_CORE#N9) U2.N12(VDD_CORE#N12) U2.N13(VDD_CORE#N13)
VDD_MPU: C41.1 C52.1 C53.1 C56.1 C83.1 C246.1 R46.2(I2) U2.F10(VDD_MPU#F10) U2.F11(VDD_MPU#F11) U2.F12(VDD_MPU#F12) U2.F13(VDD_MPU#F13) U2.G13(VDD_MPU#G13) U2.H13(VDD_MPU#H13) U2.J13(VDD_MPU#J13)
VDD_RTC: C65.1 U2.D6(CAP_VDD_RTC)
VDDA1P8V_USB0: C61.1 R502.2(I2) U2.N16(VDDA1P8V_USB0) U2.R16(VDDA1P8V_USB1)
VDDA3P3V_USB0: C62.1 R504.2(I2) U2.N15(VDDA3P3V_USB0) U2.R15(VDDA3P3V_USB1)
VDDA_ADC: FB9.1 Q5.S(SOURCE) R30.1(P1) R462.1(P1) R501.2(I2) R565.2(P2)
VDDH_PHY: C192.1 R389.1(P1) R391.2(P2) U25.10(VDDH_REG)
VDDL_PHY: C196.1 C197.1 C256.1 FB16.2 L7.1 R394.1(P1) U25.47(DVDDL)
VDDMPU_MON: R561.1(P1) U2.A2(VDD_MPU_MON)
VDDR_VREF: C303.1 C304.1 C305.1 C306.1 C307.1 C308.1 C309.2 C335.2 C336.2 R541.2(P2) R542.2(P2) U2.J4(DDR_VREF) U33.E1(VREFDQ) U33.J8(VREFCA) U34.E1(VREFDQ) U34.J8(VREFCA) U62.6(REFOUT)
VDDR_VTT: C275.1 C276.1 C277.1 C338.1 C376.1 C377.1 R598.1(P1) R599.1(P1) R600.1(P1) R601.1(P1) R602.1(P1) R603.2(P2) R604.1(P1) R605.1(P1) R606.1(P1) R607.1(P1) R608.1(P1) R609.1(P1) R610.1(P1) R611.1(P1) R612.1(P1) R613.1(P1) R614.1(P1) R615.1(P1) R616.1(P1) R617.1(P1) R618.1(P1) R619.1(P1) R620.1(P1) R621.1(P1) R622.1(P1) R623.1(P1) U62.3(VO)
VDDS_DDR: C18.1 C125.1 C126.1 C155.1 C156.1 C174.1 C181.1 C188.1 C189.1 C195.1 C202.1 C203.1 C208.1 C216.1 C217.1 C218.1 C219.1 C220.1 C221.1 C223.1 C224.1 C225.1 C226.1 C227.1 C267.1 C278.1 C279.1 C280.1 C335.1 C336.1 C339.1 C340.1 C352.2 R513.2(I2) R597.2(P2) R630.2(P2) R631.2(P2) U33.A2(VDD#A2) U33.A9(VDD#A9) U33.B9(VDDQ#B9) U33.C1(VDDQ#C1) U33.D7(VDD#D7) U33.E2(VDDQ#E2) U33.E9(VDDQ#E9) U33.G2(VDD#G2) U33.G8(VDD#G8) U33.K1(VDD#K1) U33.K9(VDD#K9) U33.M1(VDD#M1) U33.M9(VDD#M9) U34.A2(VDD#A2) U34.A9(VDD#A9) U34.B9(VDDQ#B9) U34.C1(VDDQ#C1) U34.D7(VDD#D7) U34.E2(VDDQ#E2) U34.E9(VDDQ#E9) U34.G2(VDD#G2) U34.G8(VDD#G8) U34.K1(VDD#K1) U34.K9(VDD#K9) U34.M1(VDD#M1) U34.M9(VDD#M9) U62.2(VLDOIN) U64.6(VCCB)
VDDS_OSC: C67.1 R506.1(I1) U2.R11(VDDS_OSC)
VDDS_PLL_CORE_LCD: C64.1 R503.1(I1) U2.R10(VDDS_PLL_CORE_LCD)
VDDS_PLL_DDR: C73.1 R507.2(I2) U2.E7(VDDS_PLL_DDR)
VDDS_PLL_MPU: C70.1 R497.2(I2) U2.H15(VDDS_PLL_MPU)
VDDS_RTC: C66.1 R505.1(I1) U2.D7(VDDS_RTC)
VDDS_SRAM_CORE_BG: C68.1 R500.2(I2) U2.E9(VDDS_SRAM_CORE_BG)
VDDS_SRAM_MPU_BB: C69.1 R499.2(I2) U2.D10(VDDS_SRAM_MPU_BB)
VDDSHV1: C127.1 C128.1 C129.1 C130.1 C131.1 C167.1 C169.1 FB1.1 FB2.1 R130.2(P2) R131.2(P2) R132.2(P2) R493.2(I2) R518.2(P2) U9.12(VCC#12) U9.34(VCC#34) U9.37(VCC#37) U9.39(VCC#39) U15.1(VCCA) U15.2(1DIR) U15.3(2DIR)
VDDSHV2: C15.1 C74.1 C148.1 FB5.1 J6.11 R515.2(P2) R545.2(I2) U28.5(VCCA) U28.21(VCCB0)
VDDSHV3: FB20.1 FB21.1 R546.2(I2)
VDDSHV4: C180.1 C255.1 FB4.1 J13.4(#4_MMC+/MMCM/RSMMC/MMC/SD) J13.19(#4_MINISD) R365.2(P2) R366.2(P2) R367.2(P2) R368.2(P2) R369.2(P2) R370.2(P2) R371.2(P2) R372.2(P2) R373.2(P2) R494.2(I2) U19.10(VCC) U20.10(VCC)
VDDSHV5: FB3.1 FB6.1 R388.2(P2) R409.2(P2) R495.2(I2)
VDDSHV6: C115.1 C116.1 C149.1 C163.1 C165.1 C213.1 C243.1 D8.2(ANODE) FB7.1 FB8.1 FB12.2 J2.5(TVDD) R6.2(P2) R70.2(P2) R71.2(P2) R72.2(P2) R96.2(P2) R97.2(P2) R98.2(P2) R99.2(P2) R100.2(P2) R101.2(P2) R102.2(P2) R103.2(P2) R104.2(P2) R105.2(P2) R106.2(P2) R107.2(P2) R108.2(P2) R109.2(P2) R110.2(P2) R111.2(P2) R306.2(P2) R378.2(P2) R382.1(P1) R412.1(P1) R496.2(I2) R547.2(P2) R548.2(P2) R552.2(P2) R553.2(P2) R554.2(P2) R555.2(P2) R559.2(P2) R567.2(P2) R568.2(P2) R570.2(P2) R589.2(P2) R634.2(P2) U7.8(VCC) U11.24(VCCA) U13.1(VCCA) U13.3(2DIR) U14.1(VCCA) U14.2(1DIR) U16.1(VCCA) U16.2(1DIR) U21.1(VCC) U26.5(VCC)
AM335X_AIN0: J9.14 R461.2(P2) U2.B6(AIN0)
AM335X_AIN1: J9.16 R462.2(P2) U2.C7(AIN1)
AM335X_AIN2: J9.18 U2.B7(AIN2)
AM335X_AIN3: J9.20 U2.A7(AIN3)
AM335X_AIN4: J9.13 U2.C8(AIN4)
AM335X_AIN5: J9.15 U2.B8(AIN5)
AM335X_AIN6: J9.17 U2.A8(AIN6)
AM335X_AIN7: J9.19 R23.1(P1) R571.2(P2) U2.C9(AIN7)
AM335X_ECAP0_IN_PWM0_OUT: R210.1(P1) R255.2(P2) U2.C18(ECAP0_IN_PWM0_OUT)
AM335X_EXT_WAKEUP: R67.2(P2) R207.2(P2) R405.2(P2) U2.C5(EXT_WAKEUP)
AM335X_EXTINTN: R113.1(P1) R324.2(P2) R479.2(P2) U2.B18(NMIN)
AM335X_GMII1_COL: R66.2(P2) R231.2(P2) R320.2(P2) R404.2(P2) U2.H16(MII1_COL)
AM335X_GMII1_CRS: R235.2(P2) R316.2(P2) U2.H17(MII1_CRS)
AM335X_GMII1_MDIO_CLK: R433.2(P2) U2.M18(MDIO_CLK)
AM335X_GMII1_MDIO_DATA: R434.2(P2) U2.M17(MDIO_DATA)
AM335X_GMII1_REFCLK: R188.1(P1) R321.2(P2) R410.1(P1) R432.2(P2) U2.H18(MII1_REFCLK)
AM335X_GMII1_RXCLK: R423.2(P2) U2.L18(MII1_RXCLK)
AM335X_GMII1_RXD0: R424.2(P2) U2.M16(MII1_RXD0)
AM335X_GMII1_RXD1: R425.2(P2) U2.L15(MII1_RXD1)
AM335X_GMII1_RXD2: R427.2(P2) U2.L16(MII1_RXD2)
AM335X_GMII1_RXD3: R428.2(P2) U2.L17(MII1_RXD3)
AM335X_GMII1_RXDV: R430.2(P2) U2.J17(MII1_RXDV)
AM335X_GMII1_RXERR: R237.2(P2) R317.2(P2) U2.J15(MII1_RXERR)
AM335X_GMII1_TXCLK: R415.2(P2) U2.K18(MII1_TXCLK)
AM335X_GMII1_TXD0: R416.2(P2) U2.K17(MII1_TXD0)
AM335X_GMII1_TXD1: R417.2(P2) U2.K16(MII1_TXD1)
AM335X_GMII1_TXD2: R418.2(P2) U2.K15(MII1_TXD2)
AM335X_GMII1_TXD3: R420.2(P2) U2.J18(MII1_TXD3)
AM335X_GMII1_TXEN: R421.2(P2) U2.J16(MII1_TXEN)
AM335X_GPMC_A0: R193.2(P2) R323.2(P2) R350.1(P1) R437.2(P2) U2.R13(GPMC_A0)
AM335X_GPMC_A1: R439.2(P2) R456.2(P2) U2.V14(GPMC_A1)
AM335X_GPMC_A2: R440.2(P2) R457.2(P2) U2.U14(GPMC_A2)
AM335X_GPMC_A3: R441.2(P2) R458.2(P2) U2.T14(GPMC_A3)
AM335X_GPMC_A4: R206.2(P2) R296.2(P2) R442.2(P2) U2.R14(GPMC_A4)
AM335X_GPMC_A5: R209.2(P2) R444.2(P2) R509.2(P2) U2.V15(GPMC_A5)
AM335X_GPMC_A6: R214.2(P2) R446.2(P2) U2.U15(GPMC_A6)
AM335X_GPMC_A7: R217.2(P2) R447.2(P2) R510.2(P2) U2.T15(GPMC_A7)
AM335X_GPMC_A8: R223.2(P2) R450.2(P2) R511.2(P2) U2.V16(GPMC_A8)
AM335X_GPMC_A9: R226.2(P2) R512.2(P2) U2.U16(GPMC_A9)
AM335X_GPMC_A10: R230.2(P2) R384.1(P1) U2.T16(GPMC_A10)
AM335X_GPMC_A11: R233.2(P2) U2.V17(GPMC_A11)
AM335X_GPMC_AD0: R140.2(P2) R171.1(P1) U2.U7(GPMC_AD0)
AM335X_GPMC_AD1: R141.2(P2) R169.1(P1) U2.V7(GPMC_AD1)
AM335X_GPMC_AD2: R142.2(P2) R167.1(P1) U2.R8(GPMC_AD2)
AM335X_GPMC_AD3: R143.2(P2) R165.1(P1) U2.T8(GPMC_AD3)
AM335X_GPMC_AD4: R144.2(P2) R163.1(P1) U2.U8(GPMC_AD4)
AM335X_GPMC_AD5: R145.2(P2) R161.1(P1) U2.V8(GPMC_AD5)
AM335X_GPMC_AD6: R146.2(P2) R159.1(P1) U2.R9(GPMC_AD6)
AM335X_GPMC_AD7: R147.2(P2) R157.1(P1) U2.T9(GPMC_AD7)
AM335X_GPMC_AD8: R148.2(P2) R261.2(P2) R278.2(P2) U2.U10(GPMC_AD8)
AM335X_GPMC_AD9: R149.2(P2) R263.2(P2) R286.2(P2) U2.T10(GPMC_AD9)
AM335X_GPMC_AD10: R150.2(P2) R242.2(P2) R295.2(P2) U2.T11(GPMC_AD10)
AM335X_GPMC_AD11: R151.2(P2) R243.2(P2) R279.2(P2) U2.U12(GPMC_AD11)
AM335X_GPMC_AD12: R152.2(P2) R264.2(P2) R287.2(P2) U2.T12(GPMC_AD12)
AM335X_GPMC_AD13: R153.2(P2) R247.2(P2) R297.2(P2) U2.R12(GPMC_AD13)
AM335X_GPMC_AD14: R154.2(P2) R248.2(P2) R280.2(P2) U2.V13(GPMC_AD14)
AM335X_GPMC_AD15: R155.2(P2) R253.2(P2) R298.2(P2) U2.U13(GPMC_AD15)
AM335X_GPMC_ADVN_ALE: R137.2(P2) R182.2(P2) U2.R7(GPMC_ADVN_ALE)
AM335X_GPMC_BE0N_CLE: R136.2(P2) R184.2(P2) U2.T6(GPMC_BEN0_CLE)
AM335X_GPMC_BE1N: R491.2(P2) U2.U18(GPMC_BEN1)
AM335X_GPMC_CLK: R459.2(P2) R492.1(P1) U2.V12(GPMC_CLK)
AM335X_GPMC_CS0N: R135.2(P2) R183.2(P2) U2.V6(GPMC_CSN0)
AM335X_GPMC_CS1N: R175.1(P1) U2.U9(GPMC_CSN1)
AM335X_GPMC_CS2N: R173.1(P1) U2.V9(GPMC_CSN2)
AM335X_GPMC_CS3N: R460.2(P2) U2.T13(GPMC_CSN3)
AM335X_GPMC_OEN_REN: R134.2(P2) R189.2(P2) U2.T7(GPMC_OEN_REN)
AM335X_GPMC_WAIT: R133.2(P2) R179.2(P2) U2.T17(GPMC_WAIT0)
AM335X_GPMC_WEN: R138.2(P2) R191.2(P2) U2.U6(GPMC_WEN)
AM335X_GPMC_WPN: R139.2(P2) R180.2(P2) U2.U17(GPMC_WPN)
AM335X_I2C0_SCL: R58.2(P2) R265.2(P2) R547.1(P1) R551.2(P2) U2.C16(I2C0_SCL) U7.6(SCL)
AM335X_I2C0_SDA: R59.2(P2) R268.2(P2) R548.1(P1) R550.2(P2) U2.C17(I2C0_SDA) U7.5(SDA)
AM335X_LCD_AC_BIAS_EN: R273.2(P2) R312.2(P2) U2.R6(LCD_AC_BIAS_EN)
AM335X_LCD_DATA0: R96.1(P1) R240.2(P2) R299.2(P2) SW3.16 U2.R1(LCD_DATA0)
